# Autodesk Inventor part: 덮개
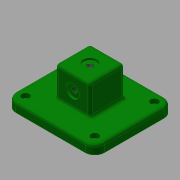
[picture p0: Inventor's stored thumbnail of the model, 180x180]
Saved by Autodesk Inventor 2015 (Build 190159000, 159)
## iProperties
Created: 2017-08
Part Number: 덮개
Material: 알루미늄 6061
Document SubType Name: Modeling
Designer: mduedu
Density: 2.71 g/cm^3
Appearance: 진녹색
Mass: 311.631 g
Surface Area: 263.031 cm^2
Volume: 114.993 cm^3
Author: mduedu
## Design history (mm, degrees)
sketch "스케치1"
  geometry: L1 (46, -41)-(-46, -41); L2 (-46, -41)-(-46, 41); L3 (-46, 41)-(46, 41); L4 (46, 41)-(46, -41); 1 further point
  constraints: 8 end point, 2 parallel, 1 horizontal, 1 perpendicular
  dimensions: "d0" = 92 distance of L2.end L3.end; "d2" = 82 distance of L1.end L2.end; "d3" = 41 distance from line of L3 point (0, 0) (= 0.5 x d2); "d4" = 46 distance from line of point (0, 0) L4 (= 0.5 x d0)
extrude "돌출1" new body sketch "스케치1" distance "d5" = 10; taper "d6" = 0 deg
sketch "스케치2"
  geometry: L1 (-18, -18)-(18, -18); L2 (18, -18)-(18, 18); L3 (18, 18)-(-18, 18); L4 (-18, 18)-(-18, -18); L5 (-18, -18)-(18, 18); L6 (18, -18)-(-18, 18); 1 further point
  constraints: 12 end point, 2 midpoint, 2 parallel, 2 perpendicular, 1 horizontal
  dimensions: "d7" = 36 distance of L2.end L3.end
extrude "돌출2" join sketch "스케치2" distance "d9" = 32; taper "d10" = 0 deg
sketch "스케치3"
  geometry: L1 (-26, -26)-(26, -26); L2 (26, -26)-(26, 26); L3 (26, 26)-(-26, 26); L4 (-26, 26)-(-26, -26); L5 (-26, -26)-(26, 26); L6 (26, -26)-(-26, 26); 1 further point
  constraints: 12 end point, 2 midpoint, 2 parallel, 2 perpendicular, 1 horizontal
  dimensions: "d11" = 52 distance of L3.end L2.end
extrude "돌출3" join sketch "스케치3" distance "d12" = 6; taper "d13" = 0 deg
sketch "스케치4"
  geometry: L1 (-17, -17)-(17, -17); L2 (17, -17)-(17, 17); L3 (17, 17)-(-17, 17); L4 (-17, 17)-(-17, -17); L5 (-17, -17)-(17, 17); L6 (17, -17)-(-17, 17); 1 further point
  constraints: 12 end point, 2 midpoint, 2 parallel, 2 perpendicular, 1 horizontal
  dimensions: "d14" = 34 distance of L2.end L3.end
extrude "돌출4" cut sketch "스케치4" distance "d16" = 5; taper "d17" = 0 deg
sketch "스케치5"
  geometry: C1 r 9 at (0, 0); 1 further point
  constraints: 1 centre point, 1 coincident
  dimensions: "d18" = 18 diameter of C1
extrude "돌출5" cut sketch "스케치5" distance "d19" = 34; taper "d20" = 0 deg
sketch "스케치6"
  geometry: 2 further points
  constraints: 1 coincident
hole "구멍1" sketch "스케치6" at (0, 0) diameter "d21" = 5.917; stored, may be unused: countersink angle "d25" = 90 deg, drill point angle "d27" = 118 deg; dims "d22" = 6, "d23" = 14, "d24" = 2, "d26" = 8
sketch "스케치7"
  geometry: L1 (-28, -10)-(64, -10) reference; 3 further points
  constraints: 1 midpoint, 1 vertical alignment
  dimensions: "d47" = 26 distance from line of point (18, 16) L1
hole "구멍2" sketch "스케치7" at (18, 16) diameter "d29" = 5.917; stored, may be unused: countersink angle "d33" = 90 deg, drill point angle "d35" = 118 deg; dims "d30" = 6, "d31" = 14, "d32" = 2, "d34" = 8
fillet "모깎기1" dims "d36" = 10
fillet "모깎기2" dims "d37" = 3
fillet "모깎기3" dims "d38" = 3
fillet "모깎기4" dims "d39" = 3
fillet "모깎기5" dims "d40" = 3
chamfer "모따기1" distance "d41" = 1; stored, may be unused: second distance "d42" = 2, angle "d43" = 45 deg
fillet "모깎기6" dims "d44" = 3
fillet "모깎기7" dims "d45" = 3
fillet "모깎기8" dims "d46" = 3
sketch "스케치8"
  geometry: A1 r 10 centre (-36, -31) between (-46, -31) and (-36, -41) reference; A2 r 10 centre (-36, 31) between (-36, 41) and (-46, 31) reference; A3 r 10 centre (36, 31) between (46, 31) and (36, 41) reference; A4 r 10 centre (36, -31) between (36, -41) and (46, -31) reference; 5 further points
  constraints: 4 coincident
sketch "스케치9"
  geometry: 4 further points
  constraints: 4 other
hole "구멍3" sketch "스케치9" at (-36, -31), (-36, 31), (36, 31), (36, -31) diameter "d48" = 4.5; stored, may be unused: countersink angle "d52" = 90 deg, drill point angle "d54" = 0 deg; dims "d49" = 6, "d50" = 8, "d51" = 4.6, "d53" = 8
node "솔리드1"
